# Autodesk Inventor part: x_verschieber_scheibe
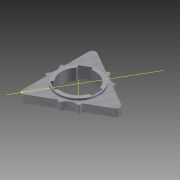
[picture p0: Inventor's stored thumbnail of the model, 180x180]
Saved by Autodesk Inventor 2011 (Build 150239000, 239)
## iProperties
Created: 2010-07
Part Number: x_verschieber_scheibe
Document SubType Name: Modeling
Designer: Mahomie
Density: 1 g/cm^3
Mass: 33.1684 g
Surface Area: 124.003 cm^2
Volume: 33.1684 cm^3
Author: Mahomie
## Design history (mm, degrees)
sketch "Skizze1" dims "d58" = 55
  geometry: L1 (-0.261, 43.714)-(116.294, 43.714); L2 (33.489, 24.229)-(-12.393, 103.698); L3 (77.239, 43.714)-(77.239, 88.458); L4 (15.551, 69.298)-(3.426, 62.298); L5 (3.426, 62.298)-(7.938, 54.484); L6 (7.938, 54.484)-(20.062, 61.484); L7 (20.062, 61.484)-(15.551, 69.298); L8 (22.239, 43.714)-(-17.225, 54.289); L9 (22.239, 43.714)-(-24.479, 31.197); L10 (22.239, 43.714)-(35.356, 92.669); L11 (22.239, 43.714)-(53.734, 75.21); L12 (22.239, 43.714)-(53.782, 12.171); L13 (22.239, 43.714)-(33.622, 1.23); L14 (-7.761, 87.016)-(-7.761, 55.503); L15 (-7.761, 31.926)-(-7.761, 0.413); L16 (74.739, 48.045)-(47.448, 63.801); L17 (27.029, 75.589)-(-0.261, 91.346); L18 (74.739, 39.384)-(47.448, 23.628); L19 (27.029, 11.839)-(-0.261, -3.917); L20 (40.586, 75.494)-(37.239, 69.695); L21 (33.489, 63.2)-(-10.704, -13.345); A1 r 5 centre (-2.761, 87.016) between (-0.261, 91.346) and (-7.761, 87.016); A2 r 5 centre (-2.761, 0.413) between (-7.761, 0.413) and (-0.261, -3.917); A3 r 5 centre (72.239, 43.714) between (74.739, 39.384) and (74.739, 48.045); A4 r 55 centre (22.239, 43.714) between (77.239, 43.714) and (-5.261, -3.917); A5 r 22.5 centre (22.239, 43.714) between (-0.261, 43.714) and (33.489, 63.2); A6 r 3.75 centre (-7.761, 35.676) between (-11.384, 34.705) and (-7.761, 31.926); A7 r 13.015 centre (-20.776, 43.714) between (-11.384, 34.705) and (-11.384, 52.724); A8 r 3.75 centre (-7.761, 51.753) between (-7.761, 55.503) and (-11.384, 52.724); A9 r 3.75 centre (30.277, 13.714) between (27.029, 11.839) and (31.248, 10.092); A10 r 13.015 centre (43.746, 6.463) between (46.852, 19.101) and (31.248, 10.092); A11 r 3.75 centre (44.2, 21.753) between (46.852, 19.101) and (47.448, 23.628); A12 r 3.75 centre (44.2, 65.676) between (47.448, 63.801) and (46.852, 68.328); A13 r 13.015 centre (43.746, 80.966) between (31.248, 77.337) and (46.852, 68.328); A14 r 3.75 centre (30.277, 73.714) between (31.248, 77.337) and (27.029, 75.589); 5 further points
  constraints: 42 end point, 33 point on circle, 14 centre point, 10 point on line, 10 tangent, 8 perpendicular, 2 coincident, 2 equal radius, 2 parallel, 2 vertical, 1 horizontal alignment, 36 other
  dimensions: "d6" = 5 radius of A1; "d9" = 86.60254 distance of A2.centre A1.centre; "d10" = 86.60254 distance of L16.start L17.end (derived); "d13" = 0 distance from line of L2 A1.centre; "d14" = 110 diameter of A4; "d16" = 30 distance of point (-7.761, 43.714) A4.centre (derived); "d17" = 55 distance of L3.start A4.centre (derived); "d20" = 45 diameter of A5; "d32" = 3 distance edge to line of A5 L4; "d33" = 14 distance of L4.start L4.end; "d34" = 7 distance between parallel lines of L2 L5; "d45" = 15 deg angle of L1 L8; "d46" = 15 deg angle of L1 L9; "d49" = 15 deg angle of L2 L12; "d50" = 15 deg angle of L2 L13; "d52" = 7.5 diameter of A6; "d55" = 360 deg dimension on L8.start A8.centre (derived); "d57" = 47.6314 vertical distance of L9.start A4.end; "d59" = 2.5 distance of point (-7.761, 43.714) point (-5.261, 43.714)
extrude "Extrusion1" new body sketch "Skizze1" distance "d18" = 10; taper "d19" = 0 deg
extrude "Extrusion2" cut sketch "Skizze1" stored distance "d21" = 10; taper "d22" = 0 deg
sketch "Skizze3"
  geometry: C1 r 22.5 at (-22.239, 43.714) reference; C2 r 27.5 at (-22.239, 43.714); 1 further point
  constraints: 1 centre point, 1 coincident
  dimensions: "d26" = 55 diameter of C2
extrude "Extrusion4" join sketch "Skizze3" distance "d27" = 2.5; taper "d28" = 0 deg
sketch "Skizze4"
  geometry: C1 r 22.5 at (22.239, 43.714) reference; C2 r 27.5 at (22.239, 43.714); 1 further point
  constraints: 1 centre point, 1 coincident
  dimensions: "d29" = 55 diameter of C2
extrude "Extrusion5" join sketch "Skizze4" distance "d30" = 2.5; taper "d31" = 0 deg
extrude "Extrusion6" cut sketch "Skizze1" stored distance "d35" = 2.5; taper "d36" = 0 deg
extrude "Extrusion7" cut sketch "Skizze1" stored distance "d37" = 2.5; taper "d38" = 0 deg
workaxis "Arbeitsachse1"
pattern_circular "Runde Anordnung1" dims angle "d40" = 360 deg
chamfer "Fase1" distance "d42" = 1; stored, may be unused: second distance "d43" = 2, angle "d44" = 45 deg
workpoint "Arbeitspunkt1"
workaxis "Arbeitsachse3"
node "Volumenkörper1"
other parameters: "d0" = 60 deg, "d1" = 60 deg, "d11" = 85 (derived), "d47" = 15 deg, "d48" = 15 deg, "d51" = 7.5
